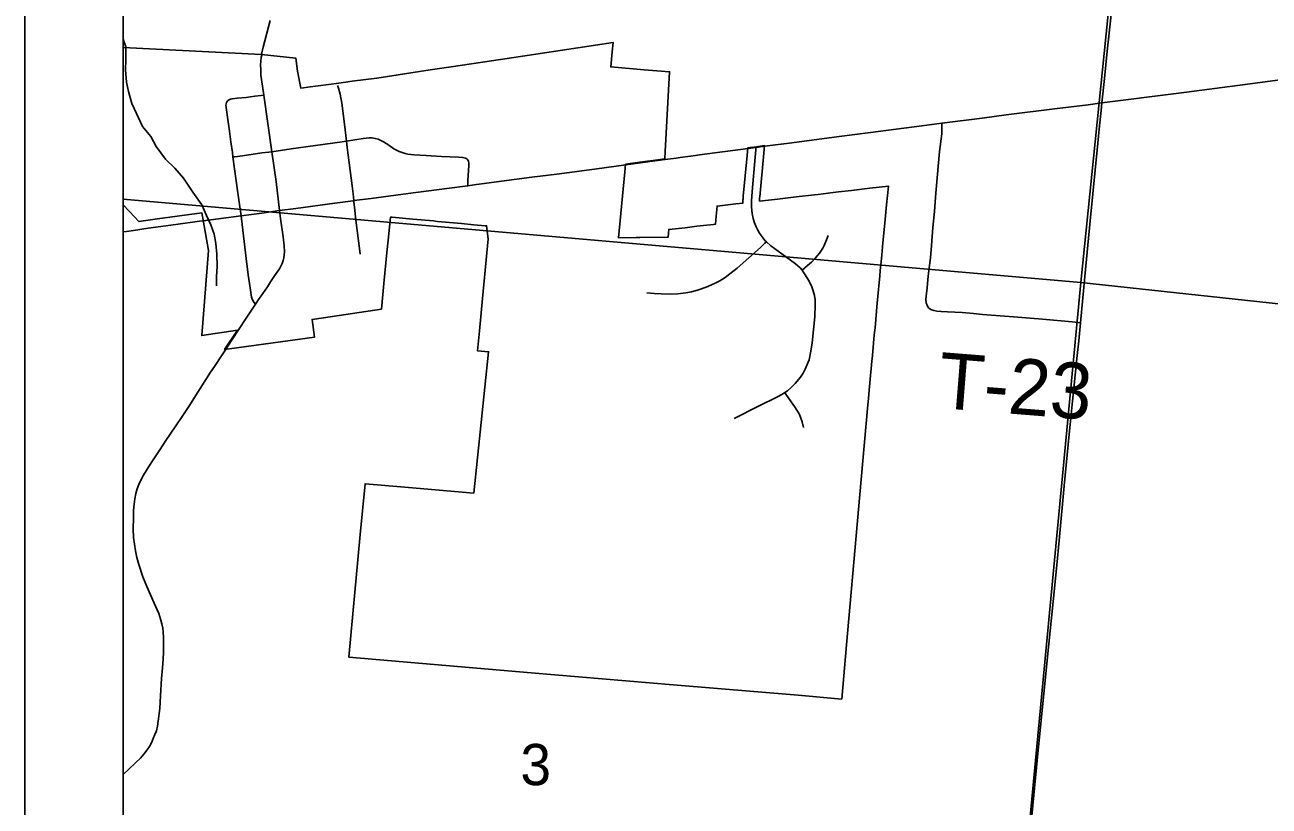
# Model space of a CAD drawing. Extents: x 0 to 34, y 0 to 22.
# Drawn here: x 2 to 3.266, y 16.978 to 17.773 of the extents above; entities that cross this region are included whole.
import ezdxf

# ---------------------------------------------------------------- set-up
doc = ezdxf.new("R2010")
doc.units = 0
for name, color, linetype in [('Default', 7, 'Continuous'), ('GM_X_City_Street', 7, 'Continuous'), ('GM_X_County_Road', 7, 'Continuous'), ('GM_X_Minor_River', 7, 'Continuous'), ('GM_X_Section', 7, 'Continuous'), ('GM_X_Section_Text', 7, 'Continuous'), ('GM_X_Township_Road', 7, 'Continuous'), ('GM_X_Township_Road_Text', 7, 'Continuous'), ('GM_X_US_Route', 7, 'Continuous'), ('SC_Shading1', 7, 'Continuous'), ('SH_Data', 7, 'Continuous')]:
    doc.layers.add(name, color=color, linetype=linetype)

msp = doc.modelspace()

# ---------------------------------------------------------------- linework, layer by layer
at = {"layer": 'Default'}
for points in [[(2.1, 17.9112), (2.1, 17.5957), (3.0746, 17.5112), (3.1795, 18.5396), (2.1707, 18.6348)], [(2.1, 17.5957), (2.1, 16.5883), (2.9781, 16.4922), (3.0746, 17.5112)]]:
    msp.add_lwpolyline(points, close=True, dxfattribs=at)
at = {"layer": 'GM_X_City_Street'}
for points in [[(2.1, 19.6388), (2.1, 15.6775)], [(2.3348, 17.5943), (2.3341, 17.6012), (2.333, 17.6094), (2.3281, 17.6483), (2.3273, 17.6549), (2.3252, 17.672), (2.3225, 17.6934), (2.3209, 17.7027), (2.3192, 17.7087), (2.318, 17.7115)], [(2.2201, 17.5789), (2.2181, 17.5928), (2.2166, 17.6022), (2.2149, 17.6143), (2.2118, 17.6387), (2.2113, 17.6432), (2.2097, 17.654), (2.2084, 17.665), (2.2069, 17.6746), (2.2047, 17.6891), (2.2046, 17.6915), (2.2048, 17.6928), (2.2051, 17.694), (2.2058, 17.6951), (2.2066, 17.696), (2.2078, 17.6968), (2.2093, 17.6975), (2.2108, 17.6979), (2.2162, 17.6986), (2.2253, 17.6993), (2.2341, 17.7006), (2.2404, 17.7012), (2.2431, 17.7015)], [(2.2513, 17.6441), (2.2711, 17.6469), (2.2957, 17.6503), (2.323, 17.6542), (2.3273, 17.6549), (2.3443, 17.6574), (2.3504, 17.6581), (2.3535, 17.6581), (2.3566, 17.6576), (2.3595, 17.6567), (2.3623, 17.6554), (2.3651, 17.654), (2.3703, 17.6506), (2.3754, 17.6471), (2.3781, 17.6457), (2.381, 17.6444), (2.3839, 17.6433), (2.3869, 17.6424), (2.3899, 17.6417), (2.396, 17.6409), (2.4084, 17.6401), (2.4239, 17.6392), (2.4413, 17.6385), (2.4454, 17.6383), (2.4484, 17.6376), (2.4499, 17.6368), (2.4509, 17.6358), (2.4515, 17.6342), (2.4518, 17.6328), (2.4519, 17.6301), (2.4508, 17.6147), (2.4509, 17.6109), (2.4509, 17.6095)], [(2.2118, 17.6387), (2.2137, 17.6389), (2.2216, 17.64), (2.241, 17.6428), (2.2484, 17.6437), (2.2513, 17.6441)], [(2.7394, 17.5922), (2.7394, 17.5937), (2.7402, 17.6037), (2.7433, 17.6385), (2.7439, 17.646), (2.744, 17.6485)], [(2.3413, 17.5399), (2.341, 17.5428), (2.3369, 17.5745), (2.3354, 17.5876), (2.3349, 17.5926), (2.3348, 17.5943)], [(2.722, 17.3728), (2.7466, 17.3852), (2.7658, 17.3948), (2.7704, 17.3973), (2.7734, 17.3992), (2.7761, 17.4009), (2.7795, 17.4039), (2.784, 17.4083), (2.7892, 17.4146), (2.7922, 17.4189), (2.7942, 17.4229), (2.7963, 17.4275), (2.7981, 17.4325), (2.8, 17.4411), (2.8012, 17.4496), (2.8038, 17.476), (2.8044, 17.4882), (2.8042, 17.4933), (2.8035, 17.4978), (2.8024, 17.5025), (2.8008, 17.5067), (2.7985, 17.5116), (2.7965, 17.5152), (2.7929, 17.5208), (2.7909, 17.5236), (2.7889, 17.5258), (2.7867, 17.528), (2.7843, 17.5301), (2.7793, 17.5339), (2.7665, 17.5429), (2.7592, 17.5482), (2.7546, 17.5525), (2.7532, 17.5538), (2.7512, 17.556), (2.7492, 17.5587), (2.7476, 17.5612), (2.7458, 17.5644), (2.7443, 17.5678), (2.7427, 17.5716), (2.7412, 17.576), (2.7401, 17.5811), (2.7395, 17.5877), (2.7394, 17.5922)], [(2.2347, 17.4889), (2.2342, 17.4895), (2.233, 17.4911), (2.2317, 17.4933), (2.2308, 17.4961), (2.2296, 17.5033), (2.2285, 17.5101), (2.2273, 17.519), (2.2252, 17.5355), (2.2225, 17.5584), (2.2205, 17.5759), (2.2201, 17.5789)], [(2.6331, 17.5007), (2.6406, 17.4998), (2.6475, 17.4994), (2.6568, 17.4992), (2.6645, 17.4996), (2.6726, 17.5005), (2.6784, 17.5015), (2.6844, 17.5033), (2.6932, 17.5063), (2.7018, 17.51), (2.7073, 17.5129), (2.7126, 17.5161), (2.7176, 17.5198), (2.7248, 17.5257), (2.7488, 17.5466), (2.753, 17.5509), (2.7546, 17.5525)], [(2.7909, 17.5236), (2.7965, 17.5283), (2.8004, 17.5318), (2.8046, 17.5362), (2.8086, 17.541), (2.812, 17.546), (2.8135, 17.5487), (2.8159, 17.5543), (2.8175, 17.5588)], [(2.7925, 17.3635), (2.791, 17.3694), (2.7895, 17.374), (2.7879, 17.3775), (2.7856, 17.3811), (2.7831, 17.385), (2.7776, 17.3931), (2.7746, 17.3974), (2.7734, 17.3992)]]:
    msp.add_lwpolyline(points, dxfattribs=at)
at = {"layer": 'GM_X_County_Road'}
msp.add_line((2.2513, 17.6441), (2.2431, 17.7015), dxfattribs=at)
for points in [[(3.137, 18.1344), (3.1382, 18.1328), (3.1389, 18.1311), (3.1394, 18.1282), (3.1395, 18.1252), (3.1388, 18.1161), (3.1353, 18.0851), (3.1272, 18.0048), (3.1178, 17.909), (3.1138, 17.8688), (3.1098, 17.8288), (3.1051, 17.7802), (3.1015, 17.7462), (3.0988, 17.7186), (3.096, 17.6937)], [(2.241, 17.7424), (2.2413, 17.7445), (2.2426, 17.7505), (2.2495, 17.7775)], [(2.2431, 17.7015), (2.2418, 17.7106), (2.2403, 17.7219), (2.24, 17.7277), (2.2399, 17.732), (2.2402, 17.7361), (2.2406, 17.7402), (2.241, 17.7424)], [(3.0742, 17.47), (3.0788, 17.5172), (3.0842, 17.5739), (3.0919, 17.6529), (3.0937, 17.6704), (3.0952, 17.686), (3.096, 17.6937)], [(2.2591, 17.5842), (2.2556, 17.6137), (2.2513, 17.6441)], [(2.2347, 17.4889), (2.2355, 17.49), (2.2379, 17.4938), (2.242, 17.4997), (2.2468, 17.5068), (2.2501, 17.5117), (2.2542, 17.5177), (2.259, 17.5251), (2.2605, 17.5278), (2.2618, 17.5305), (2.2628, 17.5333), (2.2636, 17.5362), (2.264, 17.5392), (2.2642, 17.5422), (2.2639, 17.5484), (2.2627, 17.5576), (2.2602, 17.5762), (2.2591, 17.5842)], [(2.2195, 17.4661), (2.224, 17.4727), (2.2307, 17.4828), (2.2347, 17.4889)], [(2.1929, 17.4257), (2.2008, 17.4376), (2.2021, 17.4396), (2.2117, 17.4542), (2.2167, 17.4619), (2.2195, 17.4661)], [(3.0639, 17.3666), (3.0663, 17.3905), (3.0709, 17.4369), (3.0725, 17.4517), (3.0742, 17.47)], [(2.1674, 17.3861), (2.172, 17.3931), (2.189, 17.4198), (2.1929, 17.4257)], [(2.1, 17.0108), (2.1058, 17.016), (2.1129, 17.0227), (2.1175, 17.0272), (2.1211, 17.0314), (2.1243, 17.0356), (2.1267, 17.0392), (2.1287, 17.0429), (2.1306, 17.0471), (2.1323, 17.0513), (2.1338, 17.0552), (2.135, 17.0598), (2.1358, 17.0648), (2.1372, 17.0779), (2.1381, 17.0908), (2.1392, 17.1083), (2.14, 17.119), (2.1406, 17.1281), (2.141, 17.1351), (2.1412, 17.1395), (2.1412, 17.1442), (2.1411, 17.1502), (2.1407, 17.1555), (2.1403, 17.1595), (2.1394, 17.164), (2.1385, 17.1676), (2.1363, 17.1745), (2.1316, 17.1849), (2.124, 17.202), (2.1201, 17.2118), (2.1159, 17.2241), (2.1139, 17.2312), (2.1125, 17.238), (2.1114, 17.245), (2.1106, 17.2518), (2.1103, 17.2601), (2.1104, 17.2721), (2.1107, 17.2793), (2.1112, 17.2857), (2.1119, 17.2911), (2.113, 17.2965), (2.1143, 17.3012), (2.1161, 17.3057), (2.1181, 17.3101), (2.1208, 17.315), (2.126, 17.3238), (2.1305, 17.3308), (2.1333, 17.3349), (2.1372, 17.3408), (2.1436, 17.3505), (2.1529, 17.3641), (2.1606, 17.3757), (2.1674, 17.3861)], [(2.9784, 16.4925), (2.9812, 16.5165), (2.9843, 16.5443), (2.986, 16.5637), (2.9887, 16.5938), (2.9925, 16.6309), (2.9963, 16.6679), (2.9989, 16.6938), (3.0013, 16.7176), (3.0037, 16.7471), (3.0066, 16.7788), (3.0088, 16.8036), (3.0127, 16.8437), (3.0215, 16.9333), (3.0314, 17.0353), (3.0418, 17.1403), (3.0465, 17.1867), (3.0502, 17.2237), (3.0525, 17.2485), (3.0578, 17.3041), (3.0629, 17.3567), (3.0639, 17.3666)]]:
    msp.add_lwpolyline(points, dxfattribs=at)
at = {"layer": 'GM_X_Minor_River'}
msp.add_lwpolyline([(2.1949, 17.5078), (2.195, 17.5173), (2.1956, 17.5272), (2.1953, 17.5397), (2.1943, 17.5507), (2.1925, 17.5602), (2.1892, 17.5698), (2.1848, 17.5793), (2.18, 17.59), (2.171, 17.603), (2.1613, 17.6172), (2.1527, 17.6272), (2.143, 17.6364), (2.1336, 17.6494), (2.1281, 17.6594), (2.1198, 17.6697), (2.1135, 17.6831), (2.1087, 17.693), (2.1055, 17.7052), (2.1033, 17.7147), (2.1023, 17.7273), (2.1028, 17.7375), (2.1026, 17.7508), (2.1, 17.7585)], dxfattribs=at)
at = {"layer": 'GM_X_Section'}
for points in [[(3.1795, 18.5396), (4.1385, 18.4517), (4.0957, 17.4007), (3.0746, 17.5112)], [(3.0746, 17.5112), (4.0957, 17.4007), (4.0036, 16.3979), (2.9781, 16.4922)]]:
    msp.add_lwpolyline(points, close=True, dxfattribs=at)
at = {"layer": 'GM_X_Township_Road'}
msp.add_lwpolyline([(3.0742, 17.47), (3.072, 17.4703), (3.066, 17.4709), (3.0358, 17.4736), (3.0105, 17.4757), (2.9747, 17.4785), (2.9654, 17.4794), (2.9539, 17.4804), (2.9464, 17.4808), (2.9388, 17.4812), (2.9324, 17.4815), (2.9282, 17.482), (2.925, 17.4827), (2.9221, 17.4837), (2.9197, 17.4854), (2.9182, 17.4876), (2.9173, 17.4902), (2.9169, 17.4933), (2.9172, 17.4972), (2.9182, 17.5056), (2.919, 17.5142), (2.9201, 17.5231), (2.9216, 17.5361), (2.9228, 17.5488), (2.9241, 17.567), (2.9256, 17.5834), (2.9269, 17.5977), (2.9285, 17.6174), (2.9309, 17.6444), (2.9331, 17.6624), (2.9333, 17.6663), (2.9333, 17.6694), (2.9332, 17.6718), (2.9332, 17.673)], dxfattribs=at)
at = {"layer": 'GM_X_US_Route'}
msp.add_line((2.6515, 17.6362), (2.6627, 17.6376), dxfattribs=at)
for points in [[(3.096, 17.6937), (3.1743, 17.7036), (3.242, 17.7124), (3.2851, 17.7182), (3.3313, 17.7243), (3.4084, 17.7343), (3.4969, 17.7458), (3.5431, 17.7519), (3.6274, 17.7631), (3.6817, 17.77), (3.731, 17.7766), (3.8231, 17.7887), (3.8265, 17.7892), (3.8696, 17.7949), (3.9589, 17.8067), (4.0328, 17.8165), (4.0628, 17.8205), (4.0851, 17.8235), (4.1127, 17.8273)], [(2.6825, 17.6402), (2.6865, 17.6408), (2.736, 17.6474), (2.744, 17.6485), (2.753, 17.6496), (2.7807, 17.6532), (2.8287, 17.6594), (2.8605, 17.6637), (2.9128, 17.6704), (2.9332, 17.673), (2.9742, 17.6782), (2.9988, 17.6815), (3.048, 17.6878), (3.082, 17.6919), (3.096, 17.6937)], [(2.6627, 17.6376), (2.6668, 17.6382), (2.6774, 17.6396), (2.6825, 17.6402)], [(2.4509, 17.6095), (2.4573, 17.6103), (2.485, 17.6141), (2.5158, 17.6183), (2.5413, 17.6214), (2.5798, 17.6264), (2.6117, 17.6308), (2.6339, 17.6338), (2.6361, 17.6341), (2.6515, 17.6362)], [(2.2591, 17.5842), (2.2756, 17.5864), (2.3156, 17.5918), (2.334, 17.5942), (2.3348, 17.5943), (2.3524, 17.5966), (2.3901, 17.6015), (2.4295, 17.6068), (2.4509, 17.6095)], [(2.1777, 17.5733), (2.1817, 17.5739), (2.1995, 17.5761), (2.2201, 17.5789), (2.2412, 17.5817), (2.2591, 17.5842)], [(2.1, 17.5626), (2.1035, 17.563), (2.1104, 17.564)], [(2.1104, 17.564), (2.1253, 17.5662), (2.1536, 17.5701), (2.1777, 17.5733)]]:
    msp.add_lwpolyline(points, dxfattribs=at)
at = {"layer": 'SC_Shading1'}
msp.add_lwpolyline([(2.1, 17.75), (2.1, 17.5902), (2.1119, 17.5774), (2.1158, 17.5732), (2.135, 17.5758), (2.1801, 17.5819), (2.1815, 17.5744), (2.187, 17.5436), (2.18, 17.4571), (2.2165, 17.4625), (2.2033, 17.4429), (2.2083, 17.4435), (2.2947, 17.4553), (2.2923, 17.4735), (2.304, 17.4752), (2.3629, 17.4838), (2.3654, 17.5101), (2.3683, 17.5415), (2.3697, 17.554), (2.3722, 17.5775), (2.3739, 17.5774), (2.3947, 17.5755), (2.4157, 17.5736), (2.4175, 17.5734), (2.4198, 17.5732), (2.4443, 17.571), (2.4569, 17.5698), (2.4686, 17.5688), (2.4699, 17.5687), (2.4714, 17.5553), (2.4657, 17.4947), (2.4626, 17.4618), (2.4607, 17.4415), (2.472, 17.4406), (2.4568, 17.2969), (2.3827, 17.3032), (2.3462, 17.3063), (2.3413, 17.2549), (2.3296, 17.13), (2.5152, 17.1142), (2.6597, 17.102), (2.7871, 17.0912), (2.8314, 17.0874), (2.8363, 17.1424), (2.8499, 17.2953), (2.8577, 17.383), (2.8586, 17.3935), (2.8597, 17.4053), (2.8621, 17.4309), (2.8626, 17.4368), (2.8645, 17.4579), (2.8652, 17.4651), (2.8675, 17.4904), (2.8678, 17.4934), (2.87, 17.5177), (2.8705, 17.5234), (2.8714, 17.5322), (2.872, 17.5391), (2.8731, 17.5515), (2.8751, 17.5714), (2.8769, 17.5902), (2.8788, 17.6091), (2.86, 17.6069), (2.8412, 17.6047), (2.828, 17.6031), (2.8225, 17.6025), (2.8072, 17.6007), (2.8037, 17.6003), (2.7849, 17.5981), (2.766, 17.5959), (2.7477, 17.5938), (2.7477, 17.5939), (2.7477, 17.594), (2.7477, 17.5941), (2.7477, 17.5942), (2.7477, 17.5943), (2.7477, 17.5944), (2.7477, 17.5945), (2.7477, 17.5947), (2.7477, 17.5948), (2.7477, 17.5949), (2.7477, 17.595), (2.7477, 17.5951), (2.7477, 17.5952), (2.7477, 17.5953), (2.7477, 17.5954), (2.7477, 17.5955), (2.7477, 17.5956), (2.7477, 17.5957), (2.7477, 17.5958), (2.7477, 17.596), (2.7477, 17.5961), (2.7477, 17.5962), (2.7478, 17.5963), (2.7478, 17.5964), (2.7478, 17.5965), (2.7478, 17.5966), (2.7478, 17.5967), (2.7478, 17.5968), (2.7478, 17.5969), (2.7478, 17.597), (2.7478, 17.5972), (2.7478, 17.5973), (2.7478, 17.5974), (2.7478, 17.5975), (2.7478, 17.5976), (2.7479, 17.5977), (2.7479, 17.5978), (2.7479, 17.5979), (2.7479, 17.598), (2.7479, 17.5981), (2.7479, 17.5982), (2.7521, 17.6425), (2.7528, 17.6503), (2.7486, 17.6497), (2.7445, 17.6492), (2.7387, 17.6485), (2.738, 17.6484), (2.7358, 17.6481), (2.735, 17.6403), (2.7311, 17.5987), (2.7311, 17.5985), (2.7311, 17.5984), (2.731, 17.5983), (2.731, 17.5981), (2.731, 17.598), (2.731, 17.5979), (2.731, 17.5977), (2.731, 17.5976), (2.731, 17.5975), (2.731, 17.5973), (2.731, 17.5972), (2.731, 17.5971), (2.7309, 17.5969), (2.7309, 17.5968), (2.7309, 17.5967), (2.7309, 17.5965), (2.7309, 17.5964), (2.7309, 17.5963), (2.7309, 17.5961), (2.7309, 17.596), (2.7309, 17.5959), (2.7309, 17.5957), (2.7309, 17.5956), (2.7309, 17.5954), (2.7308, 17.5953), (2.7308, 17.5952), (2.7308, 17.595), (2.7308, 17.5949), (2.7308, 17.5948), (2.7308, 17.5946), (2.7308, 17.5945), (2.7308, 17.5944), (2.7308, 17.5942), (2.7308, 17.5941), (2.7308, 17.594), (2.7308, 17.5938), (2.7308, 17.5937), (2.7308, 17.5936), (2.7308, 17.5934), (2.7308, 17.5933), (2.7308, 17.5932), (2.7308, 17.593), (2.7308, 17.5929), (2.7308, 17.5928), (2.7308, 17.5926), (2.7308, 17.5925), (2.7308, 17.5924), (2.7308, 17.5922), (2.7308, 17.5921), (2.7308, 17.5919), (2.7308, 17.5918), (2.7308, 17.5918), (2.7237, 17.591), (2.7044, 17.5887), (2.7035, 17.5785), (2.7027, 17.5703), (2.7008, 17.5701), (2.6837, 17.5682), (2.672, 17.5668), (2.6552, 17.565), (2.6546, 17.557), (2.6259, 17.5567), (2.622, 17.5567), (2.604, 17.5566), (2.6107, 17.6237), (2.6114, 17.6314), (2.6259, 17.6333), (2.6335, 17.6344), (2.6395, 17.6352), (2.6513, 17.6367), (2.6517, 17.6444), (2.6562, 17.7254), (2.6303, 17.7275), (2.5962, 17.7303), (2.5978, 17.7458), (2.5987, 17.7553), (2.4908, 17.739), (2.4362, 17.7308), (2.4123, 17.7272), (2.3583, 17.719), (2.333, 17.7157), (2.3196, 17.7139), (2.2879, 17.7098), (2.2835, 17.7092), (2.2807, 17.7088), (2.2774, 17.7261), (2.2759, 17.7392), (2.2407, 17.7428)], close=True, dxfattribs=at)
at = {"layer": 'SH_Data'}
for p, q in [((2, 21), (2, 14)), ((2.1, 20.9), (2.1, 14.1))]:
    msp.add_line(p, q, dxfattribs=at)

# ---------------------------------------------------------------- texts
at = {"layer": 'GM_X_Section_Text'}
msp.add_text('3', height=0.0419, rotation=0, dxfattribs=at).set_placement((2.5043, 16.9998))
at = {"layer": 'GM_X_Township_Road_Text'}
msp.add_text('T-23', height=0.05682, rotation=355.4669, dxfattribs=at).set_placement((2.928, 17.3836))

doc.saveas('drawing.dxf')
